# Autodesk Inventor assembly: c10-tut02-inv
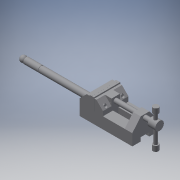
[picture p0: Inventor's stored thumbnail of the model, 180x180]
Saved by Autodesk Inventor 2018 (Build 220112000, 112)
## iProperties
Created: 2009-05
Part Number: c10-tut02-inv
Document SubType Name: Assembly
Designer: Sham
Author: Sham
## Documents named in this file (9)
- E:\_Deepak\Inventor\Autodesk Inventor_2017_Project\Resources\Inventor_2017_tut\c10_Inv_tut_2017\c10_tut02_inv\Drill Press Vice\c10-tut02-inv.iam
- E:\_Deepak\Inventor\Autodesk Inventor_2017_Project\Resources\Inventor_2017_tut\c10_Inv_tut_2017\c10_tut02_inv\Drill Press Vice\Base.ipt
- E:\_Deepak\Inventor\Autodesk Inventor_2017_Project\Resources\Inventor_2017_tut\c10_Inv_tut_2017\c10_tut02_inv\Drill Press Vice\Safety Handle.ipt
- E:\_Deepak\Inventor\Autodesk Inventor_2017_Project\Resources\Inventor_2017_tut\c10_Inv_tut_2017\c10_tut02_inv\Drill Press Vice\Jaw Face.ipt
- E:\_Deepak\Inventor\Autodesk Inventor_2017_Project\Resources\Inventor_2017_tut\c10_Inv_tut_2017\c10_tut02_inv\Drill Press Vice\Movable Jaw.ipt
- E:\_Deepak\Inventor\Autodesk Inventor_2017_Project\Resources\Inventor_2017_tut\c10_Inv_tut_2017\c10_tut02_inv\Drill Press Vice\Cap Screw.ipt
- E:\_Deepak\Inventor\Autodesk Inventor_2017_Project\Resources\Inventor_2017_tut\c10_Inv_tut_2017\c10_tut02_inv\Drill Press Vice\Clamp Screw Handle.ipt
- E:\_Deepak\Inventor\Autodesk Inventor_2017_Project\Resources\Inventor_2017_tut\c10_Inv_tut_2017\c10_tut02_inv\Drill Press Vice\Clamp Screw.ipt
- E:\_Deepak\Inventor\Autodesk Inventor_2017_Project\Resources\Inventor_2017_tut\c10_Inv_tut_2017\c10_tut02_inv\Drill Press Vice\Handle Stop.ipt
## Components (11 placed, 8 different names)
1. Base:1 — Mate:1, Flush:1, Insert:1, Insert:2, Insert:3
2. Movable Jaw:1 — Mate:1, Flush:1, Insert:4, Insert:5, Insert:6, Insert:7, Insert:8
3. Safety Handle:1 — Insert:1
4. Jaw Face:1 — Insert:4, Insert:5, Mate:7
5. Jaw Face:2 — Insert:2, Insert:3, Mate:7
6. Cap Screw:1 — Insert:7
7. Cap Screw:2 — Insert:6
8. Clamp Screw:1 — Insert:8, Mate:2
9. Clamp Screw Handle:1 — Mate:2, Insert:9, Insert:10
10. Handle Stop:1 — Insert:10
11. Handle Stop:2 — Insert:9
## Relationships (14: Insert 10, Mate 3, Flush 1)
- Mate:1: Base:1 ↔ Movable Jaw:1
- Flush:1: Base:1 ↔ Movable Jaw:1
- Insert:1: Base:1 ↔ Safety Handle:1
- Insert:2: Base:1 ↔ Jaw Face:2
- Insert:3: Base:1 ↔ Jaw Face:2
- Insert:4: Movable Jaw:1 ↔ Jaw Face:1
- Insert:5: Movable Jaw:1 ↔ Jaw Face:1
- Insert:6: Movable Jaw:1 ↔ Cap Screw:2
- Insert:7: Movable Jaw:1 ↔ Cap Screw:1
- Insert:8: Movable Jaw:1 ↔ Clamp Screw:1
- Mate:2: Clamp Screw:1 ↔ Clamp Screw Handle:1
- Insert:9: Clamp Screw Handle:1 ↔ Handle Stop:2
- Insert:10: Clamp Screw Handle:1 ↔ Handle Stop:1
- Mate:7: Jaw Face:1 ↔ Jaw Face:2
